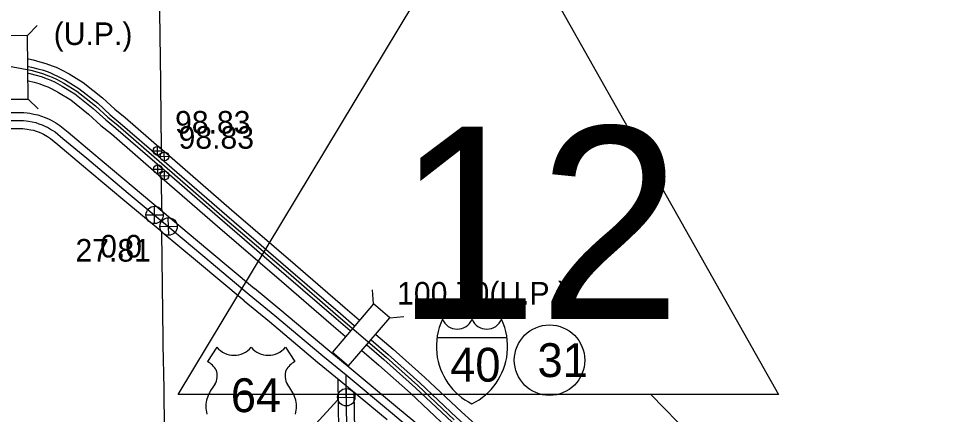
# Model space of a CAD drawing. Extents: x 31699 to 244310, y -8841 to 11474.
# Drawn here: x 99211 to 100386, y 3342 to 3836 of the extents above; entities that cross this region are included whole.
import ezdxf

# ---------------------------------------------------------------- set-up
doc = ezdxf.new("R2010")
doc.units = 0
for name, color, linetype in [('B_Logo', 7, 'Continuous'), ('Level 21', 7, 'Continuous'), ('Level 48', 7, 'Continuous'), ('New Level (0)', 7, 'Continuous'), ('R_Border Notes', 7, 'Continuous'), ('R_Logo', 7, 'Continuous'), ('R_No Plot', 7, 'Continuous'), ('R_XS_EARTHWORK_STAGE1', 7, 'Continuous'), ('R_XS_EARTHWORK_STAGE2', 7, 'Continuous'), ('S_AREA_CALC', 7, 'Continuous'), ('S_WALL', 7, 'Continuous'), ('S_WALL_ANNOT', 7, 'Continuous')]:
    doc.layers.add(name, color=color, linetype=linetype)

msp = doc.modelspace()

# ---------------------------------------------------------------- linework, layer by layer
for p, q in [((99458, 3425.7), (99446.4, 3407.8)), ((99543.8, 3425.7), (99555.3, 3407.8))]:
    msp.add_line(p, q)
for centre, radius, start, end in [((99479.5, 3443.8), 28.1, 220.075, 319.6701), ((99522.3, 3443.8), 28.1, 220.3299, 319.925), ((99431.4, 3381.9), 30, 30.7809, 59.9883), ((99570.4, 3381.9), 30, 120.0117, 149.2191), ((99438, 3389.9), 20.6, 328.8105, 21.2108), ((99563.8, 3389.9), 20.6, 158.7892, 211.1895), ((99491.7, 3347.7), 47.9, 138.9565, 162.6913), ((99510.1, 3347.7), 47.9, 17.3087, 41.0435), ((99475.9, 3351.7), 31.7, 160.9576, 197.3819), ((99525.9, 3351.7), 31.7, 342.6181, 19.0424)]:
    msp.add_arc(centre, radius, start, end)
at = {"layer": 'B_Logo'}
for points in [[(99181.1, 3780.2), (99203.3, 3775.8), (99225.5, 3771.4), (99233.3, 3769.3), (99240, 3767.3), (99247.7, 3764.5), (99252.1, 3762.8), (99257.8, 3760.1), (99266.9, 3755.3), (99283.2, 3745.3), (99306.4, 3727), (99321.9, 3712.7), (99334.7, 3702.3), (99389.2, 3655.1)], [(99181.7, 3707.7), (99199.5, 3708.6), (99210.6, 3708.7), (99216.3, 3708.7), (99219.6, 3708.4), (99222.6, 3707.9), (99227.4, 3707), (99231.8, 3706.2), (99235.7, 3704.7), (99239.8, 3703.3), (99244.1, 3701.4), (99246.3, 3700.3), (99251.6, 3697.2), (99256.1, 3694.4), (99265.8, 3686.4), (99295.5, 3661.5), (99347.1, 3618.2), (99392.3, 3580.4)], [(99389.4, 3654.9), (99467.6, 3587)], [(99467.6, 3587), (99547.4, 3518.4), (99609.7, 3464.7), (99669.4, 3413.5), (99709, 3378.1), (99754.7, 3335.1)], [(99388.7, 3583.4), (99440.5, 3540.2), (99498.6, 3491.6)], [(99498.6, 3491.6), (99530.4, 3465.5), (99590.3, 3415), (99619.4, 3391.2), (99677.3, 3343), (99715.5, 3311.1)], [(99620.5, 3322.3), (99619.4, 3391.2)]]:
    msp.add_lwpolyline(points, dxfattribs=at)
at = {"layer": 'Level 21'}
for p, q in [((99378.5, 3671), (99389.4, 3671)), ((99383.9, 3665.6), (99383.9, 3676.4)), ((99392.6, 3658.5), (99392.3, 3669.4)), ((99387, 3663.8), (99397.9, 3664.1)), ((99378.9, 3647.9), (99389.8, 3647.9)), ((99384.3, 3642.5), (99384.3, 3653.3)), ((99392.8, 3634.5), (99392.6, 3645.4)), ((99387.3, 3639.8), (99398.1, 3640.1)), ((99380.3, 3579.9), (99380.3, 3601.6)), ((99369.4, 3590.8), (99391.1, 3590.8)), ((99397.9, 3565.6), (99397.4, 3587.3)), ((99386.8, 3576.2), (99408.5, 3576.7)), ((99619.9, 3352.4), (99619.4, 3374.1)), ((99608.8, 3363), (99630.5, 3363.5))]:
    msp.add_line(p, q, dxfattribs=at)
for centre, radius in [((99383.9, 3671), 5.42), ((99392.5, 3663.9), 5.43), ((99384.3, 3647.9), 5.42), ((99392.7, 3639.9), 5.43), ((99380.3, 3590.8), 10.8), ((99397.7, 3576.4), 10.9), ((99619.7, 3363.3), 10.9)]:
    msp.add_circle(centre, radius, dxfattribs=at)
at = {"layer": 'Level 48'}
msp.add_line((100000.1, 3366.8), (102655.5, 673.9), dxfattribs=at)
msp.add_lwpolyline([(99409.9, 3366.8), (99797.1, 4009.1), (100159.9, 3366.8)], close=True, dxfattribs=at)
at = {"layer": 'New Level (0)'}
for points in [[(99222.7, 3785.5), (99228.5, 3784.4), (99236.9, 3782.1), (99244.2, 3780), (99252.4, 3776.9), (99257.3, 3775.1), (99263.8, 3772), (99273.5, 3766.9), (99290.8, 3756.3), (99315.1, 3737.1), (99330.7, 3722.8), (99343.3, 3712.6), (99388.8, 3673.1)], [(99222.5, 3776.2), (99226.4, 3775.4), (99234.4, 3773.3), (99241.3, 3771.3), (99249.2, 3768.4), (99253.7, 3766.7), (99259.7, 3763.8), (99268.9, 3758.9), (99285.6, 3748.8), (99309.2, 3730.2), (99324.7, 3715.9), (99337.4, 3705.5), (99388.6, 3661.1)], [(99222.9, 3767.6), (99224.5, 3767.3), (99232.2, 3765.3), (99238.7, 3763.4), (99246.2, 3760.5), (99250.5, 3759), (99255.9, 3756.4), (99264.8, 3751.7), (99280.8, 3741.9), (99303.7, 3723.8), (99319.2, 3709.6), (99332, 3699.1), (99389.7, 3649.1)], [(99222.9, 3758.3), (99229.7, 3756.4), (99235.8, 3754.7), (99243, 3752), (99246.9, 3750.5), (99251.8, 3748.2), (99260.3, 3743.7), (99275.6, 3734.4), (99297.8, 3716.8), (99313.2, 3702.6), (99326.2, 3692.1), (99389, 3637.5)], [(99389.1, 3672.8), (99476.4, 3597.1)], [(99389.1, 3660.6), (99470.4, 3590.1)], [(99389.2, 3649.6), (99464.9, 3583.8)], [(99389.4, 3637.2), (99458.9, 3576.9)], [(99476.3, 3597.1), (99556.1, 3528.5), (99618.4, 3474.8), (99635.8, 3459.9)], [(99464.9, 3583.8), (99544.6, 3515.2), (99607, 3461.5), (99624.4, 3446.5)], [(99470.3, 3590.1), (99550.1, 3521.5), (99612.4, 3467.8), (99629.8, 3452.9)], [(99458.9, 3576.9), (99538.7, 3508.3), (99601, 3454.5), (99618.4, 3439.6)], [(99650.9, 3434.9), (99672.1, 3416.6), (99711.8, 3381.2), (99757.5, 3338.2), (99822, 3280.1), (99872.9, 3232), (99900, 3205.7), (99921.3, 3186), (99926.1, 3180.5), (99932.3, 3175), (99937, 3171), (99942.4, 3166.6), (99947.8, 3162.9), (99953.2, 3159.4), (99973.5, 3150.2), (100015.1, 3132.7), (100052.6, 3116.8)], [(99656.8, 3441.8), (99678.2, 3423.5), (99718, 3388), (99763.7, 3345), (99828.2, 3286.8), (99879.2, 3238.6), (99906.3, 3212.4), (99927.9, 3192.4), (99932.6, 3186.9), (99938.3, 3181.9), (99942.8, 3178.1), (99947.9, 3174), (99952.9, 3170.5), (99957.6, 3167.4), (99977.2, 3158.6), (100018.7, 3141.2), (100056.4, 3125.1)], [(99639.3, 3421.7), (99660.6, 3403.5), (99700, 3368.3), (99745.7, 3325.3), (99810.1, 3267.2), (99860.8, 3219.3), (99887.9, 3193), (99908.7, 3173.8), (99913.6, 3168.1), (99920.8, 3161.7), (99925.9, 3157.5), (99931.9, 3152.6), (99938, 3148.4), (99944.7, 3144), (99966.5, 3134.1), (100008.3, 3116.6), (100045.7, 3100.7)], [(99645.4, 3428.6), (99666.7, 3410.4), (99706.2, 3375.1), (99751.9, 3332.1), (99816.3, 3274), (99867.1, 3226), (99894.2, 3199.7), (99915.3, 3180.2), (99920.1, 3174.6), (99926.8, 3168.6), (99931.7, 3164.6), (99937.4, 3160), (99943.1, 3156), (99949.1, 3152), (99970.2, 3142.5), (100011.9, 3125.1), (100049.2, 3109.2)]]:
    msp.add_lwpolyline(points, dxfattribs=at)
at = {"layer": 'R_Border Notes'}
msp.add_circle((99873.7, 3409.6), 44, dxfattribs=at)
at = {"layer": 'R_Logo'}
for points in [[(99388, 3756.5), (99385.4, 3932.2), (99385.2, 3934.1), (99384, 4105.6), (99383.9, 4110.5), (99382.1, 4287.1), (99380.9, 4462.2), (99380.9, 4464.3), (99379.7, 4550.5)], [(99388, 3756.5), (99385.4, 3932.2), (99385.2, 3934.1), (99384, 4105.6), (99383.9, 4110.5), (99382.1, 4287.1), (99380.9, 4462.2), (99380.9, 4464.3), (99379.7, 4547.2)], [(99388.7, 3672.8), (99388.1, 3753.5), (99388, 3756.5)], [(99388.7, 3673.5), (99388.1, 3753.5), (99388, 3756.5)], [(99389.4, 3595.6), (99389, 3637.2)], [(99389.3, 3596.7), (99389, 3636.9)], [(99399.9, 2869.2), (99397.2, 3049.4), (99397, 3050.5), (99393.8, 3226.2), (99391.9, 3400.5), (99391.5, 3403), (99389.5, 3569.5)], [(99399.9, 2869.2), (99397.2, 3049.4), (99397, 3050.5), (99393.8, 3226.2), (99391.9, 3400.5), (99391.5, 3403), (99389.5, 3569.1)]]:
    msp.add_lwpolyline(points, dxfattribs=at)
at = {"layer": 'R_No Plot'}
msp.add_line((99733.1, 3437.8), (99820.5, 3437.8), dxfattribs=at)
for centre, radius, start, end in [((99814.3, 3426.4), 82, 155.2204, 185.7928), ((99758.4, 3468.3), 20, 202.1459, 337.3414), ((99795.3, 3468.3), 20, 202.6586, 337.8541), ((99739.3, 3426.4), 82, 354.2072, 24.7796), ((99812.8, 3427.1), 80.6, 186.3923, 243.4571), ((99740.8, 3427.1), 80.6, 296.5429, 353.6077)]:
    msp.add_arc(centre, radius, start, end, dxfattribs=at)
at = {"layer": 'R_XS_EARTHWORK_STAGE1'}
for p, q in [((99221.3, 3814.7), (99233.6, 3827.3)), ((99222.2, 3735.5), (99234.8, 3723.2)), ((99653.9, 3479.7), (99652.6, 3497.3)), ((99653.9, 3479.7), (99602.4, 3419.6)), ((99674, 3462.5), (99653.9, 3479.7)), ((99622.4, 3402.4), (99674, 3462.5)), ((99674, 3462.5), (99691.5, 3463.9)), ((99602.4, 3419.6), (99622.4, 3402.4))]:
    msp.add_line(p, q, dxfattribs=at)
msp.add_lwpolyline([(99194.9, 3814.4), (99195.8, 3735.2), (99222.2, 3735.5), (99221.3, 3814.7)], close=True, dxfattribs=at)
at = {"layer": 'R_XS_EARTHWORK_STAGE2'}
for points in [[(99610.5, 3322.2), (99609.5, 3385.5)], [(99630.5, 3322.4), (99629.8, 3369.1)]]:
    msp.add_lwpolyline(points, dxfattribs=at)
at = {"layer": 'S_AREA_CALC'}
for points in [[(99181.2, 3717.7), (99199.3, 3718.6), (99210.5, 3718.7), (99216.9, 3718.7), (99220.9, 3718.3), (99224.2, 3717.8), (99229.2, 3716.8), (99234.5, 3715.8), (99239.1, 3714.1), (99243.4, 3712.6), (99248.4, 3710.5), (99251.2, 3709.1), (99256.7, 3705.7), (99261.9, 3702.6), (99272.2, 3694.1), (99301.9, 3669.1), (99353.5, 3625.9), (99389.6, 3595.7)], [(99182.2, 3697.8), (99199.8, 3698.6), (99210.7, 3698.7), (99215.8, 3698.7), (99218.3, 3698.4), (99220.9, 3698), (99225.5, 3697.2), (99229.1, 3696.5), (99232.3, 3695.3), (99236.2, 3694), (99239.9, 3692.4), (99241.4, 3691.6), (99246.4, 3688.6), (99250.3, 3686.2), (99259.4, 3678.7), (99289, 3653.8), (99340.7, 3610.5), (99389.6, 3569.7)], [(99389.7, 3595.6), (99446.9, 3547.9), (99505, 3499.2)], [(99389.8, 3569.5), (99434, 3532.6), (99492.2, 3483.9)], [(99505, 3499.3), (99536.8, 3473.1), (99596.7, 3422.7), (99625.8, 3398.9), (99683.7, 3350.7), (99721.9, 3318.7)], [(99492.3, 3483.8), (99524, 3457.8), (99583.9, 3407.3), (99613, 3383.5), (99670.9, 3335.4)]]:
    msp.add_lwpolyline(points, dxfattribs=at)
at = {"layer": 'S_WALL_ANNOT'}
msp.add_line((99557.4, 3304.2), (99608.8, 3359.6), dxfattribs=at)

# ---------------------------------------------------------------- texts
msp.add_text('64', height=42.24).set_placement((99475.5, 3344.7))
at = {"layer": 'Level 48'}
msp.add_text('12', height=240, dxfattribs=at).set_placement((99681.2, 3460.9))
at = {"layer": 'R_Border Notes'}
msp.add_text('31', height=42.24, dxfattribs=at).set_placement((99858.7, 3388.5))
at = {"layer": 'R_No Plot'}
msp.add_text('40', height=42.24, dxfattribs=at).set_placement((99749.6, 3382.8))
at = {"layer": 'S_WALL'}
for s, p in [('(U.P.)', (99254.2, 3802.9)), ('100.70(U.P.)', (99683.3, 3479))]:
    msp.add_text(s, height=28.16, dxfattribs=at).set_placement(p)
at = {"layer": 'S_WALL_ANNOT'}
for s, p in [('98.83', (99405.8, 3692.4)), ('98.83', (99410.2, 3673.5)), ('27.81', (99281.4, 3532.6)), ('0.0', (99312.2, 3537.7))]:
    msp.add_text(s, height=28.16, dxfattribs=at).set_placement(p)

doc.saveas('drawing.dxf')
